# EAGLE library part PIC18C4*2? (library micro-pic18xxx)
High-Performance Microcontrollers with 10-Bit A/D
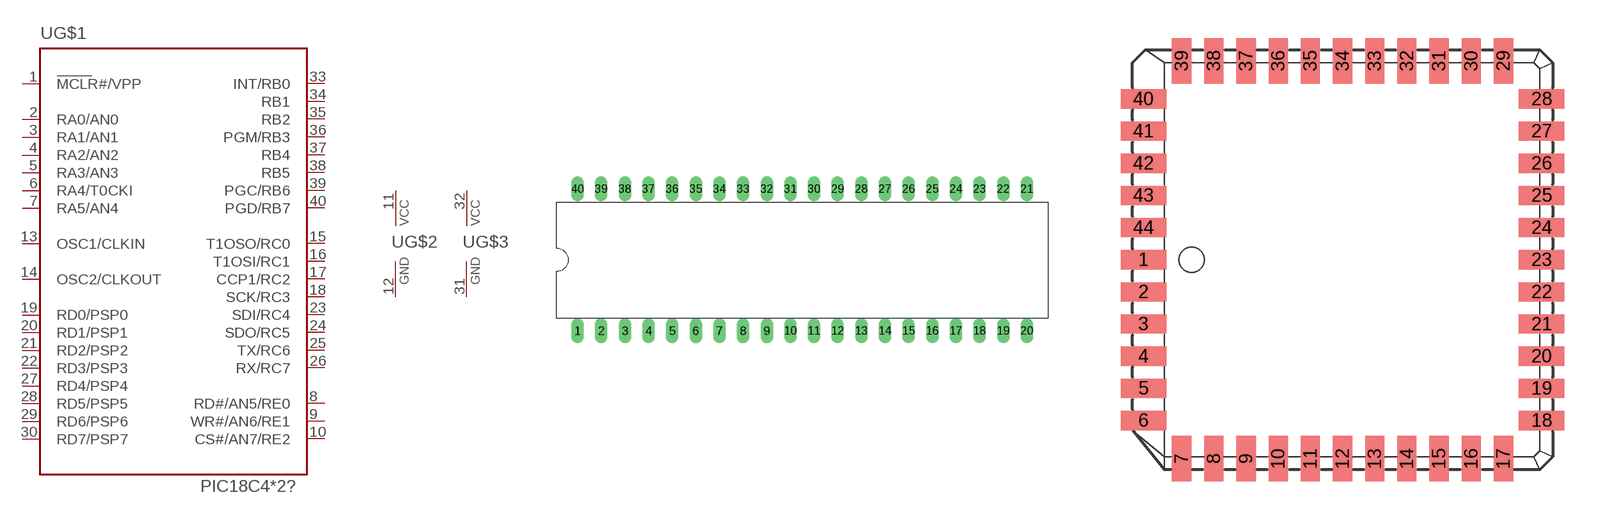
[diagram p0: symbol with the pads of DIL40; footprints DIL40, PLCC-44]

Designator prefix -; gates G$1=ABCDE G$2=GNDVCC G$3=GNDVCC

## PIC18C442P, PIC18C452P  [DIL40]
1  G$1:MCLR#/VPP  in
2  G$1:RA0/AN0
3  G$1:RA1/AN1
4  G$1:RA2/AN2
5  G$1:RA3/AN3
6  G$1:RA4/T0CKI
7  G$1:RA5/AN4
8  G$1:RD#/AN5/RE0
9  G$1:WR#/AN6/RE1
10  G$1:CS#/AN7/RE2
11  G$2:VCC  pwr
12  G$2:GND  pwr
13  G$1:OSC1/CLKIN  in
14  G$1:OSC2/CLKOUT  out
15  G$1:T1OSO/RC0
16  G$1:T1OSI/RC1
17  G$1:CCP1/RC2
18  G$1:SCK/RC3
19  G$1:RD0/PSP0
20  G$1:RD1/PSP1
21  G$1:RD2/PSP2
22  G$1:RD3/PSP3
23  G$1:SDI/RC4
24  G$1:SDO/RC5
25  G$1:TX/RC6
26  G$1:RX/RC7
27  G$1:RD4/PSP4
28  G$1:RD5/PSP5
29  G$1:RD6/PSP6
30  G$1:RD7/PSP7
31  G$3:GND  pwr
32  G$3:VCC  pwr
33  G$1:INT/RB0
34  G$1:RB1
35  G$1:RB2
36  G$1:PGM/RB3
37  G$1:RB4
38  G$1:RB5
39  G$1:PGC/RB6
40  G$1:PGD/RB7

## PIC18C442L, PIC18C452L  [PLCC-44]
2  G$1:MCLR#/VPP  in
3  G$1:RA0/AN0
4  G$1:RA1/AN1
5  G$1:RA2/AN2
6  G$1:RA3/AN3
7  G$1:RA4/T0CKI
8  G$1:RA5/AN4
9  G$1:RD#/AN5/RE0
10  G$1:WR#/AN6/RE1
11  G$1:CS#/AN7/RE2
12  G$2:VCC  pwr
13  G$2:GND  pwr
14  G$1:OSC1/CLKIN  in
15  G$1:OSC2/CLKOUT  out
16  G$1:T1OSO/RC0
18  G$1:T1OSI/RC1
19  G$1:CCP1/RC2
20  G$1:SCK/RC3
21  G$1:RD0/PSP0
22  G$1:RD1/PSP1
23  G$1:RD2/PSP2
24  G$1:RD3/PSP3
25  G$1:SDI/RC4
26  G$1:SDO/RC5
27  G$1:TX/RC6
29  G$1:RX/RC7
30  G$1:RD4/PSP4
31  G$1:RD5/PSP5
32  G$1:RD6/PSP6
33  G$1:RD7/PSP7
34  G$3:GND  pwr
35  G$3:VCC  pwr
36  G$1:INT/RB0
37  G$1:RB1
38  G$1:RB2
39  G$1:PGM/RB3
41  G$1:RB4
42  G$1:RB5
43  G$1:PGC/RB6
44  G$1:PGD/RB7

## PIC18C442PT, PIC18C452PT  [TQFP44]
1  G$1:RX/RC7
2  G$1:RD4/PSP4
3  G$1:RD5/PSP5
4  G$1:RD6/PSP6
5  G$1:RD7/PSP7
6  G$2:VCC  pwr
7  G$2:GND  pwr
8  G$1:INT/RB0
9  G$1:RB1
10  G$1:RB2
11  G$1:PGM/RB3
14  G$1:RB4
15  G$1:RB5
16  G$1:PGC/RB6
17  G$1:PGD/RB7
18  G$1:MCLR#/VPP  in
19  G$1:RA0/AN0
20  G$1:RA1/AN1
21  G$1:RA2/AN2
22  G$1:RA3/AN3
23  G$1:RA4/T0CKI
24  G$1:RA5/AN4
25  G$1:RD#/AN5/RE0
26  G$1:WR#/AN6/RE1
27  G$1:CS#/AN7/RE2
28  G$3:GND  pwr
29  G$3:VCC  pwr
30  G$1:OSC1/CLKIN  in
31  G$1:OSC2/CLKOUT  out
32  G$1:T1OSO/RC0
35  G$1:T1OSI/RC1
36  G$1:CCP1/RC2
37  G$1:SCK/RC3
38  G$1:RD0/PSP0
39  G$1:RD1/PSP1
40  G$1:RD2/PSP2
41  G$1:RD3/PSP3
42  G$1:SDI/RC4
43  G$1:SDO/RC5
44  G$1:TX/RC6

## Footprint DIL40 (pad centres in mm)
DIL package type P
drill 0.813 long: 1 -24.13,-7.62; 2 -21.59,-7.62; 3 -19.05,-7.62; 4 -16.51,-7.62; 5 -13.97,-7.62; 6 -11.43,-7.62; 7 -8.89,-7.62; 8 -6.35,-7.62; 9 -3.81,-7.62; 10 -1.27,-7.62; 11 1.27,-7.62; 12 3.81,-7.62; 13 6.35,-7.62; 14 8.89,-7.62; 15 11.43,-7.62; 16 13.97,-7.62; 17 16.51,-7.62; 18 19.05,-7.62; 19 21.59,-7.62; 20 24.13,-7.62; 21 24.13,7.62; 22 21.59,7.62; 23 19.05,7.62; 24 16.51,7.62; 25 13.97,7.62; 26 11.43,7.62; 27 8.89,7.62; 28 6.35,7.62; 29 3.81,7.62; 30 1.27,7.62; 31 -1.27,7.62; 32 -3.81,7.62; 33 -6.35,7.62; 34 -8.89,7.62; 35 -11.43,7.62; 36 -13.97,7.62; 37 -16.51,7.62; 38 -19.05,7.62; 39 -21.59,7.62; 40 -24.13,7.62

## Footprint PLCC-44 (pad centres in mm)
Plastic LCC square package type L
smd 1.8 x 0.76: 1 -7.86,0; 2 -7.86,-1.27; 3 -7.86,-2.54; 4 -7.86,-3.81; 5 -7.86,-5.08; 6 -7.86,-6.35; 18 7.86,-6.35; 19 7.86,-5.08; 20 7.86,-3.81; 21 7.86,-2.54; 22 7.86,-1.27; 23 7.86,0; 24 7.86,1.27; 25 7.86,2.54; 26 7.86,3.81; 27 7.86,5.08; 28 7.86,6.35; 40 -7.86,6.35; 41 -7.86,5.08; 42 -7.86,3.81; 43 -7.86,2.54; 44 -7.86,1.27
smd 0.76 x 1.8: 7 -6.35,-7.86; 8 -5.08,-7.86; 9 -3.81,-7.86; 10 -2.54,-7.86; 11 -1.27,-7.86; 12 0,-7.86; 13 1.27,-7.86; 14 2.54,-7.86; 15 3.81,-7.86; 16 5.08,-7.86; 17 6.35,-7.86; 29 6.35,7.86; 30 5.08,7.86; 31 3.81,7.86; 32 2.54,7.86; 33 1.27,7.86; 34 0,7.86; 35 -1.27,7.86; 36 -2.54,7.86; 37 -3.81,7.86; 38 -5.08,7.86; 39 -6.35,7.86

## Footprint TQFP44 (pad centres in mm)
TQFP package type TQ
smd 1.5 x 0.5: 1 -5.8,4; 2 -5.8,3.2; 3 -5.8,2.4; 4 -5.8,1.6; 5 -5.8,0.8; 6 -5.8,0; 7 -5.8,-0.8; 8 -5.8,-1.6; 9 -5.8,-2.4; 10 -5.8,-3.2; 11 -5.8,-4; 23 5.8,-4; 24 5.8,-3.2; 25 5.8,-2.4; 26 5.8,-1.6; 27 5.8,-0.8; 28 5.8,0; 29 5.8,0.8; 30 5.8,1.6; 31 5.8,2.4; 32 5.8,3.2; 33 5.8,4
smd 0.5 x 1.5: 12 -4,-5.8; 13 -3.2,-5.8; 14 -2.4,-5.8; 15 -1.6,-5.8; 16 -0.8,-5.8; 17 0,-5.8; 18 0.8,-5.8; 19 1.6,-5.8; 20 2.4,-5.8; 21 3.2,-5.8; 22 4,-5.8; 34 4,5.8; 35 3.2,5.8; 36 2.4,5.8; 37 1.6,5.8; 38 0.8,5.8; 39 0,5.8; 40 -0.8,5.8; 41 -1.6,5.8; 42 -2.4,5.8; 43 -3.2,5.8; 44 -4,5.8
